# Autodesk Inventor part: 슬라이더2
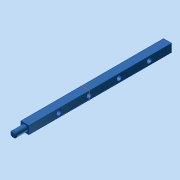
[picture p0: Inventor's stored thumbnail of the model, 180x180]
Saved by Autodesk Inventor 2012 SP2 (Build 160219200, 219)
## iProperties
Company: 한국ATC센터
Created: 2015-04
Part Number: 슬라이더2
Document SubType Name: Modeling
Designer: KYOUNG IL JANG
Density: 7.85 g/cm^3
Material: 강
Author: KYOUNG IL JANG
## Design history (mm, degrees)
sketch "스케치3"
  geometry: L1 (4, 142)-(-4, 142); L2 (-4, 142)-(-4, 0); L3 (-4, 0)-(4, 0); L4 (4, 0)-(4, 142); 3 further points
  constraints: 8 end point, 2 coincident, 2 parallel, 1 horizontal, 1 midpoint, 1 perpendicular
  dimensions: "d5" = 8 distance of L1.start L1.end; "d6" = 142 distance of L1.end L2.end
extrude "돌출3" new body sketch "스케치3" stored distance "d7" = 8; taper "d8" = 0 deg
sketch "스케치4"
  geometry: L1 (8, 0)-(0, 0) reference; 3 further points
  constraints: 1 midpoint, 1 vertical alignment
  dimensions: "d9" = 30 distance of point (4, 30) point (4, 0)
hole "구멍1" sketch "스케치4" at (4, 30) diameter "d10" = 5; stored, may be unused: countersink angle "d14" = 90 deg, drill point angle "d16" = 118 deg; dims "d11" = 6, "d12" = 4, "d13" = 2, "d15" = 8
sketch "스케치5"
  geometry: C1 r 3 at (4, -4); 1 further point
  constraints: 1 centre point, 1 coincident
  dimensions: "d20" = 6 diameter of C1
extrude "돌출4" join sketch "스케치5" distance "d21" = 12; taper "d22" = 0 deg
chamfer "모따기1" distance "d23" = 1; stored, may be unused: second distance "d24" = 2, angle "d25" = 45 deg
node "작업 평면2"
  node "작업축1"
node "솔리드1"
pattern_linear "직사각형 패턴1" dims "d19" = 30
node "솔리드2"
other parameters: "d26" = 0
